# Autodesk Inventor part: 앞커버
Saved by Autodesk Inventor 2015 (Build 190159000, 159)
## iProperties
Created: 2025-08
Part Number: 앞커버
Material: 일반
Document SubType Name: Modeling
Designer: user
Density: 1 g/cm^3
Appearance: 기본값
Author: jhkim
Creation Date: 2025-08-05
Sending System: Autodesk Inventor 2026
Preprocessor: ST-DEVELOPER v20.1
Author: user
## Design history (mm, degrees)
node "앞커버1"
node "솔리드1"
node "기준1"
